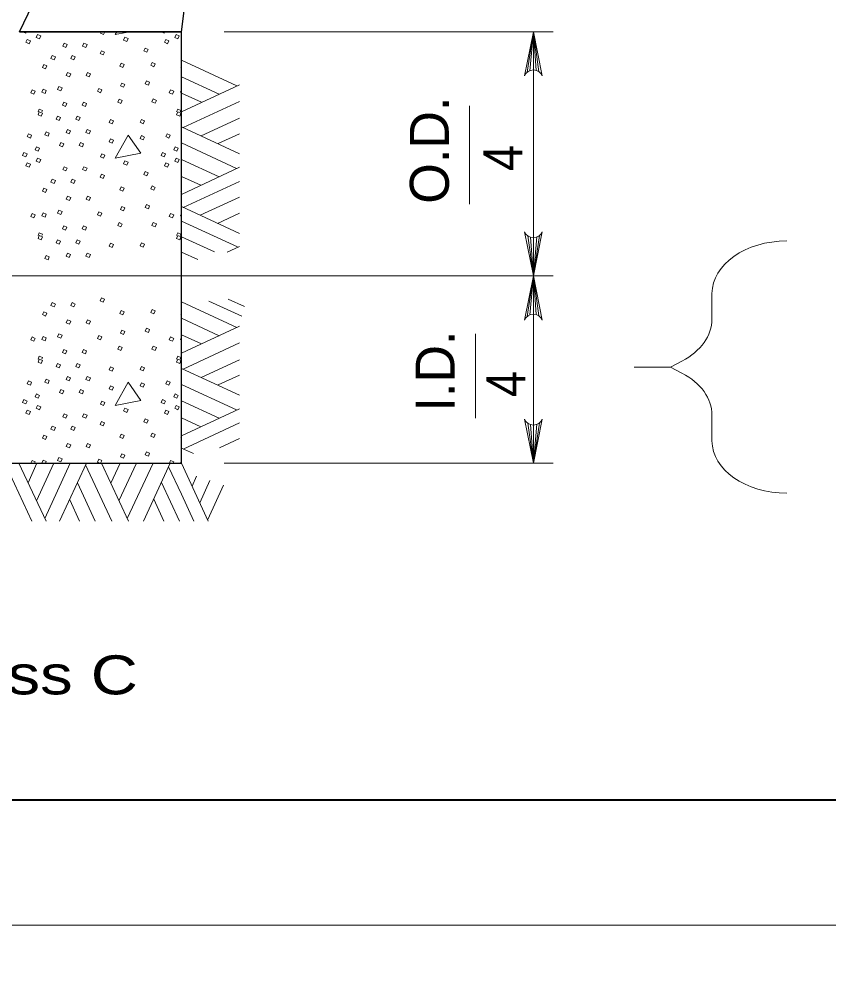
# Model space of a CAD drawing. Extents: x 1083.1 to 1117.1, y 697.4 to 741.4.
# Drawn here: x 1094.266 to 1097.505, y 719.104 to 722.978 of the extents above; entities that cross this region are included whole.
import ezdxf
from ezdxf.enums import TextEntityAlignment as Align

# ---------------------------------------------------------------- set-up
doc = ezdxf.new("R2010")
doc.units = 0
doc.header["$LTSCALE"] = 0.062
doc.linetypes.add('LONG_DASHED', pattern=[7.5, 6, -1.5])
doc.layers.add('1', color=7, linetype='Continuous', lineweight=13)

msp = doc.modelspace()

# ---------------------------------------------------------------- linework, layer by layer
at = {"layer": '1', "lineweight": 25}
for p, q in [((1094.915, 722.92817), (1095.17642, 725.01283)), ((1094.26642, 722.92817), (1094.915, 722.92817)), ((1094.26642, 722.92817), (1094.915, 722.92817))]:
    msp.add_line(p, q, dxfattribs=at)
at = {"layer": '1'}
for p, q in [((1094.915, 722.92817), (1094.26642, 722.92817)), ((1095.08633, 722.92817), (1096.40183, 722.92817)), ((1096.29833, 722.76608), (1096.32317, 722.92817)), ((1096.30875, 722.77217), (1096.32317, 722.92817)), ((1096.32317, 722.775), (1096.32317, 722.92817)), ((1096.3345, 722.77333), (1096.32317, 722.92817)), ((1096.34558, 722.76792), (1096.32317, 722.92817)), ((1094.915, 722.81433), (1095.13617, 722.71133)), ((1094.915, 722.74808), (1095.06567, 722.67817)), ((1094.915, 722.60825), (1095.14708, 722.71633)), ((1094.915, 722.68242), (1094.995, 722.64575)), ((1094.9215, 722.54483), (1095.14708, 722.64933)), ((1094.34125, 722.60725), (1094.34625, 722.61867)), ((1094.89558, 722.60725), (1094.90058, 722.61867)), ((1096.06708, 722.63183), (1096.06708, 722.23783)), ((1094.99358, 722.51175), (1095.14708, 722.58225)), ((1094.915, 722.54775), (1095.14708, 722.44033)), ((1095.06133, 722.48142), (1095.14708, 722.52033)), ((1094.915, 722.48358), (1095.1355, 722.38133)), ((1094.915, 722.41725), (1095.06567, 722.34817)), ((1094.915, 722.2775), (1095.14708, 722.38633)), ((1094.915, 722.3495), (1094.99283, 722.31425)), ((1094.92217, 722.22492), (1095.14708, 722.32942)), ((1094.98925, 722.19392), (1095.14708, 722.26667)), ((1094.915, 722.2285), (1095.14783, 722.12117)), ((1095.05917, 722.1615), (1095.14708, 722.20183)), ((1094.915, 722.17083), (1095.13983, 722.06708)), ((1094.34125, 722.11283), (1094.34625, 722.12425)), ((1094.89558, 722.11283), (1094.90058, 722.12425)), ((1094.915, 722.1075), (1095.04683, 722.04733)), ((1096.30075, 722.1115), (1096.32317, 721.95125)), ((1096.34792, 722.11342), (1096.32317, 721.95125)), ((1096.33758, 722.10725), (1096.32317, 721.95125)), ((1095.0985, 722.04683), (1095.14708, 722.06925)), ((1096.31183, 722.10608), (1096.32317, 721.95125)), ((1096.32317, 722.10442), (1096.32317, 721.95125)), ((1094.915, 722.04617), (1094.98, 722.0165)), ((1093.40175, 721.95125), (1096.40183, 721.95125)), ((1096.29833, 721.78908), (1096.32317, 721.95125)), ((1096.30875, 721.79525), (1096.32317, 721.95125)), ((1096.32317, 721.79808), (1096.32317, 721.95125)), ((1096.3345, 721.79642), (1096.32317, 721.95125)), ((1096.34558, 721.791), (1096.32317, 721.95125)), ((1097.03783, 721.88125), (1097.03783, 721.7785)), ((1094.915, 721.848), (1095.13617, 721.745)), ((1095.02442, 721.85092), (1095.15625, 721.79075)), ((1095.102, 721.85808), (1095.16692, 721.82833)), ((1094.915, 721.78175), (1095.06567, 721.71192)), ((1094.915, 721.64192), (1095.14708, 721.75008)), ((1096.09108, 721.71983), (1096.09108, 721.38208)), ((1094.915, 721.71617), (1094.995, 721.67942)), ((1094.9215, 721.57858), (1095.14708, 721.683)), ((1094.34125, 721.61833), (1094.34625, 721.62975)), ((1094.89558, 721.61833), (1094.90058, 721.62975)), ((1094.99358, 721.54542), (1095.14708, 721.61608)), ((1096.87208, 721.5865), (1096.91767, 721.6105)), ((1094.915, 721.5815), (1095.14708, 721.474)), ((1096.87208, 721.5865), (1096.7265, 721.5865)), ((1096.87208, 721.5865), (1096.91767, 721.5625)), ((1095.06133, 721.51508), (1095.14708, 721.55408)), ((1094.915, 721.51733), (1095.1355, 721.415)), ((1094.915, 721.45108), (1095.06567, 721.38175)), ((1094.915, 721.31125), (1095.14708, 721.42008)), ((1094.915, 721.38325), (1094.99283, 721.348)), ((1097.03783, 721.3945), (1097.03783, 721.29183)), ((1094.92217, 721.25867), (1095.14708, 721.36308)), ((1096.30075, 721.36192), (1096.32317, 721.20167)), ((1096.31183, 721.3565), (1096.32317, 721.20167)), ((1096.34792, 721.36383), (1096.32317, 721.20167)), ((1096.33758, 721.35767), (1096.32317, 721.20167)), ((1096.32317, 721.35483), (1096.32317, 721.20167)), ((1095.0675, 721.26375), (1095.14708, 721.30042)), ((1094.915, 721.26225), (1094.96267, 721.24025)), ((1094.21167, 721.1945), (1094.31617, 720.96958)), ((1094.26425, 721.20167), (1094.37308, 720.96958)), ((1094.33625, 721.20167), (1094.301, 721.12383)), ((1094.3125, 721.20167), (1094.31725, 721.2125)), ((1094.40408, 721.20167), (1094.33492, 721.05108)), ((1094.47033, 721.20167), (1094.36808, 720.98125)), ((1094.5345, 721.20167), (1094.42717, 720.96958)), ((1094.53158, 721.19517), (1094.63617, 720.96958)), ((1094.59508, 721.20167), (1094.70308, 720.96958)), ((1094.66925, 721.20167), (1094.63258, 721.12175)), ((1094.73492, 721.20167), (1094.66492, 721.05108)), ((1094.80117, 721.20167), (1094.69808, 720.9805)), ((1094.87033, 721.20167), (1094.763, 720.96958)), ((1094.86383, 721.18733), (1094.915, 721.07775)), ((1094.86683, 721.20167), (1094.87158, 721.2125)), ((1094.915, 721.20167), (1095.02233, 720.96958)), ((1095.08633, 721.20167), (1096.40183, 721.20167)), ((1094.97575, 721.15008), (1094.9575, 721.11017)), ((1094.4985, 721.12317), (1094.56908, 720.96958)), ((1094.83508, 721.12533), (1094.90783, 720.96958)), ((1095.02892, 721.1325), (1094.9885, 721.04392)), ((1095.08375, 721.11442), (1095.02025, 720.97683)), ((1094.915, 721.07775), (1094.96467, 720.96958)), ((1094.46825, 721.05533), (1094.50708, 720.96958)), ((1094.80408, 721.05825), (1094.84433, 720.96958))]:
    msp.add_line(p, q, dxfattribs=at)
at = {"layer": '1', "linetype": 'LONG_DASHED'}
for points in [[(1083.12642, 719.35408), (1117.12642, 719.35408), (1117.12642, 741.35408), (1083.12642, 741.35408)], [(1083.12642, 697.35408), (1117.12642, 697.35408), (1117.12642, 719.35408), (1083.12642, 719.35408)]]:
    msp.add_lwpolyline(points, close=True, dxfattribs=at)
at = {"layer": '1', "lineweight": 25}
for points in [[(1116.62642, 719.85408), (1085.12642, 719.85408), (1085.12642, 740.85408)], [(1091.06575, 722.92817), (1090.41717, 722.92817), (1090.41717, 721.20167), (1094.915, 721.20167), (1094.915, 722.92817)], [(1090.41717, 722.92817), (1090.41717, 721.20167), (1094.915, 721.20167), (1094.915, 722.92817), (1094.26642, 722.92817)]]:
    msp.add_lwpolyline(points, dxfattribs=at)
at = {"layer": '1', "lineweight": 40}
msp.add_lwpolyline([(1085.12642, 740.85408), (1116.62642, 740.85408), (1116.62642, 719.85408), (1085.12642, 719.85408)], close=True, dxfattribs=at)
msp.add_lwpolyline([(1085.12642, 740.85408), (1116.62642, 740.85408), (1116.62642, 719.85408), (1085.12642, 719.85408)], close=True, dxfattribs=at)
at = {"layer": '1'}
for points in [[(1094.29442, 722.92817), (1094.29192, 722.92242), (1094.27942, 722.92783), (1094.27958, 722.92817)], [(1094.60842, 722.92817), (1094.60342, 722.91675), (1094.59092, 722.92217), (1094.59358, 722.92817)], [(1094.65608, 722.92817), (1094.64958, 722.91667), (1094.70842, 722.92817)], [(1094.84875, 722.92817), (1094.84625, 722.92242), (1094.83375, 722.92783), (1094.83392, 722.92817)], [(1096.28775, 722.75117), (1096.32317, 722.92817), (1096.35858, 722.75117)], [(1096.32317, 722.92817), (1096.32317, 721.95125), (1096.32317, 721.20167)], [(1094.915, 722.78442), (1094.91317, 722.78525), (1094.915, 722.78958)], [(1094.915, 722.68442), (1094.911, 722.68617), (1094.915, 722.69542)], [(1094.34625, 722.61867), (1094.35875, 722.61325), (1094.35617, 722.60725)], [(1094.90058, 722.61867), (1094.913, 722.61325), (1094.9105, 722.60725)], [(1094.915, 722.29), (1094.91317, 722.29083), (1094.915, 722.29508)], [(1094.915, 722.18992), (1094.911, 722.19167), (1094.915, 722.201)], [(1094.34625, 722.12425), (1094.35875, 722.11883), (1094.35617, 722.11283)], [(1094.90058, 722.12425), (1094.913, 722.11883), (1094.9105, 722.11283)], [(1096.35858, 722.12825), (1096.32317, 721.95125), (1096.28775, 722.12825)], [(1096.28775, 721.77425), (1096.32317, 721.95125), (1096.35858, 721.77425)], [(1094.915, 721.7955), (1094.91317, 721.79633), (1094.915, 721.80067)], [(1094.915, 721.6955), (1094.911, 721.69725), (1094.915, 721.7065)], [(1094.34625, 721.62975), (1094.35875, 721.62433), (1094.35617, 721.61833)], [(1094.90058, 721.62975), (1094.913, 721.62433), (1094.9105, 721.61833)], [(1096.35858, 721.37867), (1096.32317, 721.20167), (1096.28775, 721.37867)], [(1094.915, 721.30108), (1094.91317, 721.30183), (1094.915, 721.30617)], [(1094.58958, 721.20167), (1094.57883, 721.20633), (1094.584, 721.21817)], [(1094.584, 721.21817), (1094.5965, 721.21275), (1094.59167, 721.20167)], [(1094.31725, 721.2125), (1094.32975, 721.20708), (1094.32733, 721.20167)], [(1094.35908, 721.20167), (1094.35667, 721.20275), (1094.36183, 721.21458)], [(1094.36183, 721.21458), (1094.37433, 721.20917), (1094.371, 721.20167)], [(1094.87158, 721.2125), (1094.88408, 721.20708), (1094.88167, 721.20167)], [(1094.91342, 721.20167), (1094.911, 721.20275), (1094.915, 721.212)]]:
    msp.add_lwpolyline(points, dxfattribs=at)
for points in [[(1094.29808, 722.89758), (1094.31058, 722.89217), (1094.30542, 722.88033), (1094.29292, 722.88575)], [(1094.33917, 722.91675), (1094.35167, 722.91133), (1094.3465, 722.8995), (1094.334, 722.90492)], [(1094.44533, 722.88275), (1094.45783, 722.87742), (1094.45267, 722.86558), (1094.44017, 722.871)], [(1094.52458, 722.88275), (1094.53708, 722.87742), (1094.53192, 722.86558), (1094.51942, 722.871)], [(1094.68883, 722.90608), (1094.70133, 722.90067), (1094.69617, 722.88883), (1094.68367, 722.89425)], [(1094.85242, 722.89758), (1094.86492, 722.89217), (1094.85975, 722.88033), (1094.84725, 722.88575)], [(1094.8935, 722.91675), (1094.906, 722.91133), (1094.90083, 722.8995), (1094.88833, 722.90492)], [(1094.59467, 722.85233), (1094.60717, 722.84692), (1094.602, 722.83508), (1094.5895, 722.8405)], [(1094.7695, 722.863), (1094.782, 722.85758), (1094.77683, 722.84575), (1094.76433, 722.85117)], [(1094.39792, 722.83325), (1094.41042, 722.82783), (1094.40525, 722.816), (1094.39275, 722.82142)], [(1094.47717, 722.83325), (1094.48967, 722.82783), (1094.4845, 722.816), (1094.472, 722.82142)], [(1094.79717, 722.80558), (1094.80967, 722.80017), (1094.8045, 722.78833), (1094.792, 722.79375)], [(1094.364, 722.79708), (1094.3765, 722.79167), (1094.37133, 722.77983), (1094.35883, 722.78525)], [(1094.67325, 722.80208), (1094.68575, 722.79667), (1094.68058, 722.78483), (1094.66808, 722.79025)], [(1094.4595, 722.7645), (1094.472, 722.75908), (1094.46683, 722.74725), (1094.45433, 722.75267)], [(1094.53875, 722.7645), (1094.55125, 722.75908), (1094.54608, 722.74725), (1094.53358, 722.75267)], [(1094.77517, 722.73125), (1094.78767, 722.72592), (1094.7825, 722.71408), (1094.77, 722.7195)], [(1094.31725, 722.69592), (1094.32975, 722.6905), (1094.32458, 722.67867), (1094.31208, 722.68408)], [(1094.36183, 722.698), (1094.37433, 722.69258), (1094.36917, 722.68075), (1094.35667, 722.68617)], [(1094.42483, 722.70867), (1094.43733, 722.70325), (1094.43217, 722.69142), (1094.41967, 722.69683)], [(1094.584, 722.70158), (1094.5965, 722.69617), (1094.59133, 722.68433), (1094.57883, 722.68975)], [(1094.67617, 722.723), (1094.68867, 722.71758), (1094.6835, 722.70575), (1094.671, 722.71117)], [(1094.87158, 722.69592), (1094.88408, 722.6905), (1094.87892, 722.67867), (1094.86642, 722.68408)], [(1094.66575, 722.65883), (1094.67825, 722.65342), (1094.67308, 722.64158), (1094.66058, 722.647)], [(1094.80208, 722.65908), (1094.81458, 722.65367), (1094.80942, 722.64183), (1094.79692, 722.64725)], [(1094.44392, 722.64633), (1094.45642, 722.64092), (1094.45125, 722.62908), (1094.43875, 722.6345)], [(1094.52317, 722.64633), (1094.53567, 722.64092), (1094.5305, 722.62908), (1094.518, 722.6345)], [(1094.34625, 722.60725), (1094.35875, 722.60183), (1094.35358, 722.59008), (1094.34108, 722.59542)], [(1094.41842, 722.59033), (1094.43092, 722.58492), (1094.42575, 722.57308), (1094.41325, 722.5785)], [(1094.49767, 722.59033), (1094.51017, 722.58492), (1094.505, 722.57308), (1094.4925, 722.5785)], [(1094.63075, 722.57692), (1094.64325, 722.5715), (1094.63808, 722.55967), (1094.62558, 722.56508)], [(1094.75467, 722.57758), (1094.76717, 722.57217), (1094.762, 722.56033), (1094.7495, 722.56575)], [(1094.90058, 722.60725), (1094.913, 722.60183), (1094.90792, 722.59008), (1094.89542, 722.59542)], [(1094.45883, 722.53725), (1094.47133, 722.53183), (1094.46617, 722.52), (1094.45367, 722.52542)], [(1094.53808, 722.53725), (1094.55058, 722.53183), (1094.54542, 722.52), (1094.53292, 722.52542)], [(1094.30308, 722.52025), (1094.31558, 722.51483), (1094.31042, 722.503), (1094.29792, 722.50842)], [(1094.37392, 722.52733), (1094.38633, 722.52192), (1094.38125, 722.51008), (1094.36875, 722.5155)], [(1094.6305, 722.50017), (1094.643, 722.49475), (1094.63783, 722.48292), (1094.62533, 722.48833)], [(1094.70183, 722.51483), (1094.64958, 722.42225), (1094.75183, 722.44225)], [(1094.75467, 722.51242), (1094.76717, 722.507), (1094.762, 722.49517), (1094.7495, 722.50058)], [(1094.85742, 722.52025), (1094.86992, 722.51483), (1094.86475, 722.503), (1094.85225, 722.50842)], [(1094.33492, 722.46783), (1094.34742, 722.46242), (1094.34225, 722.45058), (1094.32975, 722.456)], [(1094.43192, 722.4855), (1094.44442, 722.48008), (1094.43925, 722.46825), (1094.42675, 722.47367)], [(1094.51117, 722.4855), (1094.52367, 722.48008), (1094.5185, 722.46825), (1094.506, 722.47367)], [(1094.88925, 722.46783), (1094.90175, 722.46242), (1094.89658, 722.45058), (1094.88408, 722.456)], [(1094.28458, 722.44525), (1094.29708, 722.43983), (1094.29192, 722.428), (1094.27942, 722.43342)], [(1094.33917, 722.42233), (1094.35167, 722.41692), (1094.3465, 722.40508), (1094.334, 722.4105)], [(1094.59608, 722.43958), (1094.60858, 722.43417), (1094.60342, 722.42233), (1094.59092, 722.42775)], [(1094.83892, 722.44525), (1094.85142, 722.43983), (1094.84625, 722.428), (1094.83375, 722.43342)], [(1094.8935, 722.42233), (1094.906, 722.41692), (1094.90083, 722.40508), (1094.88833, 722.4105)], [(1094.29808, 722.40317), (1094.31058, 722.39775), (1094.30542, 722.38592), (1094.29292, 722.39133)], [(1094.44533, 722.38833), (1094.45783, 722.38292), (1094.45267, 722.37108), (1094.44017, 722.3765)], [(1094.52458, 722.38833), (1094.53708, 722.38292), (1094.53192, 722.37108), (1094.51942, 722.3765)], [(1094.68883, 722.41167), (1094.70133, 722.40625), (1094.69617, 722.39442), (1094.68367, 722.39983)], [(1094.85242, 722.40317), (1094.86492, 722.39775), (1094.85975, 722.38592), (1094.84725, 722.39133)], [(1094.39792, 722.33875), (1094.41042, 722.33333), (1094.40525, 722.3215), (1094.39275, 722.32692)], [(1094.47717, 722.33875), (1094.48967, 722.33333), (1094.4845, 722.3215), (1094.472, 722.32692)], [(1094.59467, 722.35783), (1094.60717, 722.35242), (1094.602, 722.34058), (1094.5895, 722.346)], [(1094.7695, 722.3685), (1094.782, 722.36308), (1094.77683, 722.35125), (1094.76433, 722.35667)], [(1094.364, 722.30267), (1094.3765, 722.29725), (1094.37133, 722.28542), (1094.35883, 722.29083)], [(1094.67325, 722.30758), (1094.68575, 722.30217), (1094.68058, 722.29042), (1094.66808, 722.29583)], [(1094.79717, 722.31108), (1094.80967, 722.30567), (1094.8045, 722.29392), (1094.792, 722.29933)], [(1094.4595, 722.27008), (1094.472, 722.26467), (1094.46683, 722.25283), (1094.45433, 722.25825)], [(1094.53875, 722.27008), (1094.55125, 722.26467), (1094.54608, 722.25283), (1094.53358, 722.25825)], [(1094.67617, 722.2285), (1094.68867, 722.22308), (1094.6835, 722.21125), (1094.671, 722.21667)], [(1094.77517, 722.23683), (1094.78767, 722.23142), (1094.7825, 722.21958), (1094.77, 722.225)], [(1094.31725, 722.20142), (1094.32975, 722.196), (1094.32458, 722.18417), (1094.31208, 722.18958)], [(1094.36183, 722.2035), (1094.37433, 722.19808), (1094.36917, 722.18625), (1094.35667, 722.19167)], [(1094.42483, 722.21417), (1094.43733, 722.20875), (1094.43217, 722.19692), (1094.41967, 722.20233)], [(1094.584, 722.20708), (1094.5965, 722.20167), (1094.59133, 722.18983), (1094.57883, 722.19525)], [(1094.87158, 722.20142), (1094.88408, 722.196), (1094.87892, 722.18417), (1094.86642, 722.18958)], [(1094.44392, 722.15192), (1094.45642, 722.1465), (1094.45125, 722.13467), (1094.43875, 722.14008)], [(1094.52317, 722.15192), (1094.53567, 722.1465), (1094.5305, 722.13467), (1094.518, 722.14008)], [(1094.66575, 722.16433), (1094.67825, 722.15892), (1094.67308, 722.14717), (1094.66058, 722.15258)], [(1094.80208, 722.16458), (1094.81458, 722.15917), (1094.80942, 722.14742), (1094.79692, 722.15283)], [(1094.34625, 722.11283), (1094.35875, 722.10742), (1094.35358, 722.09558), (1094.34108, 722.101)], [(1094.90058, 722.11283), (1094.913, 722.10742), (1094.90792, 722.09558), (1094.89542, 722.101)], [(1094.41842, 722.09583), (1094.43092, 722.09042), (1094.42575, 722.07858), (1094.41325, 722.084)], [(1094.49767, 722.09583), (1094.51017, 722.09042), (1094.505, 722.07858), (1094.4925, 722.084)], [(1094.63075, 722.08242), (1094.64325, 722.077), (1094.63808, 722.06517), (1094.62558, 722.07058)], [(1094.75467, 722.08308), (1094.76717, 722.07767), (1094.762, 722.06583), (1094.7495, 722.07125)], [(1094.37392, 722.03283), (1094.38633, 722.02742), (1094.38125, 722.01567), (1094.36875, 722.021)], [(1094.45883, 722.04275), (1094.47133, 722.03733), (1094.46617, 722.0255), (1094.45367, 722.03092)], [(1094.53808, 722.04275), (1094.55058, 722.03733), (1094.54542, 722.0255), (1094.53292, 722.03092)], [(1094.39792, 721.84433), (1094.41042, 721.83892), (1094.40525, 721.82708), (1094.39275, 721.8325)], [(1094.47717, 721.84433), (1094.48967, 721.83892), (1094.4845, 721.82708), (1094.472, 721.8325)], [(1094.59467, 721.86342), (1094.60717, 721.858), (1094.602, 721.84617), (1094.5895, 721.85158)], [(1094.364, 721.80817), (1094.3765, 721.80275), (1094.37133, 721.79092), (1094.35883, 721.79633)], [(1094.67325, 721.81317), (1094.68575, 721.80775), (1094.68058, 721.79592), (1094.66808, 721.80133)], [(1094.79717, 721.81667), (1094.80967, 721.81125), (1094.8045, 721.79942), (1094.792, 721.80483)], [(1094.4595, 721.77558), (1094.472, 721.77017), (1094.46683, 721.75833), (1094.45433, 721.76375)], [(1094.53875, 721.77558), (1094.55125, 721.77017), (1094.54608, 721.75833), (1094.53358, 721.76375)], [(1094.42483, 721.71975), (1094.43733, 721.71433), (1094.43217, 721.7025), (1094.41967, 721.70792)], [(1094.67617, 721.734), (1094.68867, 721.72858), (1094.6835, 721.71683), (1094.671, 721.72225)], [(1094.77517, 721.74233), (1094.78767, 721.73692), (1094.7825, 721.72517), (1094.77, 721.7305)], [(1094.31725, 721.707), (1094.32975, 721.70158), (1094.32458, 721.68975), (1094.31208, 721.69517)], [(1094.36183, 721.70908), (1094.37433, 721.70367), (1094.36917, 721.69183), (1094.35667, 721.69725)], [(1094.584, 721.71267), (1094.5965, 721.70725), (1094.59133, 721.69542), (1094.57883, 721.70083)], [(1094.87158, 721.707), (1094.88408, 721.70158), (1094.87892, 721.68975), (1094.86642, 721.69517)], [(1094.44392, 721.65742), (1094.45642, 721.652), (1094.45125, 721.64017), (1094.43875, 721.64558)], [(1094.52317, 721.65742), (1094.53567, 721.652), (1094.5305, 721.64017), (1094.518, 721.64558)], [(1094.66575, 721.66992), (1094.67825, 721.6645), (1094.67308, 721.65267), (1094.66058, 721.65808)], [(1094.80208, 721.67017), (1094.81458, 721.66475), (1094.80942, 721.65292), (1094.79692, 721.65833)], [(1094.34625, 721.61833), (1094.35875, 721.61292), (1094.35358, 721.60108), (1094.34108, 721.6065)], [(1094.90058, 721.61833), (1094.913, 721.61292), (1094.90792, 721.60108), (1094.89542, 721.6065)], [(1094.41842, 721.60133), (1094.43092, 721.59592), (1094.42575, 721.58417), (1094.41325, 721.5895)], [(1094.49767, 721.60133), (1094.51017, 721.59592), (1094.505, 721.58417), (1094.4925, 721.5895)], [(1094.63075, 721.58792), (1094.64325, 721.58258), (1094.63808, 721.57075), (1094.62558, 721.57617)], [(1094.75467, 721.58858), (1094.76717, 721.58325), (1094.762, 721.57142), (1094.7495, 721.57683)], [(1094.30308, 721.53133), (1094.31558, 721.52592), (1094.31042, 721.51408), (1094.29792, 721.5195)], [(1094.37392, 721.53842), (1094.38633, 721.533), (1094.38125, 721.52117), (1094.36875, 721.52658)], [(1094.45883, 721.54833), (1094.47133, 721.54292), (1094.46617, 721.53108), (1094.45367, 721.5365)], [(1094.53808, 721.54833), (1094.55058, 721.54292), (1094.54542, 721.53108), (1094.53292, 721.5365)], [(1094.70183, 721.52592), (1094.64958, 721.43333), (1094.75183, 721.45325)], [(1094.85742, 721.53133), (1094.86992, 721.52592), (1094.86475, 721.51408), (1094.85225, 721.5195)], [(1094.43192, 721.49658), (1094.44442, 721.49117), (1094.43925, 721.47933), (1094.42675, 721.48475)], [(1094.51117, 721.49658), (1094.52367, 721.49117), (1094.5185, 721.47933), (1094.506, 721.48475)], [(1094.6305, 721.51125), (1094.643, 721.50583), (1094.63783, 721.494), (1094.62533, 721.49942)], [(1094.75467, 721.5235), (1094.76717, 721.51808), (1094.762, 721.50625), (1094.7495, 721.51167)], [(1094.28458, 721.45625), (1094.29708, 721.45083), (1094.29192, 721.43908), (1094.27942, 721.44442)], [(1094.33492, 721.47892), (1094.34742, 721.4735), (1094.34225, 721.46167), (1094.32975, 721.46708)], [(1094.59608, 721.45058), (1094.60858, 721.44517), (1094.60342, 721.43342), (1094.59092, 721.43883)], [(1094.83892, 721.45625), (1094.85142, 721.45083), (1094.84625, 721.43908), (1094.83375, 721.44442)], [(1094.88925, 721.47892), (1094.90175, 721.4735), (1094.89658, 721.46167), (1094.88408, 721.46708)], [(1094.29808, 721.41425), (1094.31058, 721.40883), (1094.30542, 721.397), (1094.29292, 721.40242)], [(1094.33917, 721.43342), (1094.35167, 721.428), (1094.3465, 721.41617), (1094.334, 721.42158)], [(1094.68883, 721.42275), (1094.70133, 721.41733), (1094.69617, 721.4055), (1094.68367, 721.41092)], [(1094.85242, 721.41425), (1094.86492, 721.40883), (1094.85975, 721.397), (1094.84725, 721.40242)], [(1094.8935, 721.43342), (1094.906, 721.428), (1094.90083, 721.41617), (1094.88833, 721.42158)], [(1094.44533, 721.39942), (1094.45783, 721.394), (1094.45267, 721.38217), (1094.44017, 721.38758)], [(1094.52458, 721.39942), (1094.53708, 721.394), (1094.53192, 721.38217), (1094.51942, 721.38758)], [(1094.7695, 721.37958), (1094.782, 721.37417), (1094.77683, 721.36233), (1094.76433, 721.36775)], [(1094.39792, 721.34983), (1094.41042, 721.34442), (1094.40525, 721.33258), (1094.39275, 721.338)], [(1094.47717, 721.34983), (1094.48967, 721.34442), (1094.4845, 721.33258), (1094.472, 721.338)], [(1094.59467, 721.36892), (1094.60717, 721.3635), (1094.602, 721.35167), (1094.5895, 721.35708)], [(1094.364, 721.31367), (1094.3765, 721.30825), (1094.37133, 721.2965), (1094.35883, 721.30183)], [(1094.67325, 721.31867), (1094.68575, 721.31325), (1094.68058, 721.30142), (1094.66808, 721.30683)], [(1094.79717, 721.32217), (1094.80967, 721.31675), (1094.8045, 721.30492), (1094.792, 721.31033)], [(1094.4595, 721.28117), (1094.472, 721.27575), (1094.46683, 721.26392), (1094.45433, 721.26933)], [(1094.53875, 721.28117), (1094.55125, 721.27575), (1094.54608, 721.26392), (1094.53358, 721.26933)], [(1094.42483, 721.22525), (1094.43733, 721.21983), (1094.43217, 721.208), (1094.41967, 721.21342)], [(1094.67617, 721.23958), (1094.68867, 721.23417), (1094.6835, 721.22233), (1094.671, 721.22775)], [(1094.77517, 721.24792), (1094.78767, 721.2425), (1094.7825, 721.23067), (1094.77, 721.23608)]]:
    msp.add_lwpolyline(points, close=True, dxfattribs=at)
for centre, start, end in [((1096.32319, 722.7369), 22.08782, 157.91395), ((1096.32311, 722.14255), 202.08782, 337.91395), ((1096.32319, 721.75996), 22.08782, 157.91395), ((1096.32311, 721.39298), 202.08782, 337.91395)]:
    msp.add_arc(centre, 0.0382, start, end, dxfattribs=at)
at = {"layer": '1', "lineweight": 25}
msp.add_ellipse((1092.66607, 723.75022), major_axis=(1.79915, 0), ratio=0.999895, start_param=5.8086305, end_param=9.8993328, dxfattribs=at)
msp.add_ellipse((1092.66607, 723.75022), major_axis=(1.79915, 0), ratio=0.999895, start_param=5.8086305, end_param=9.8993328, dxfattribs=at)
at = {"layer": '1'}
for centre, major_axis, start_param, end_param in [((1097.33771, 721.88123), (-0.29986, 0), 4.712389, 6.2831853), ((1096.73799, 721.77852), (0.29986, 0), 5.3548956, 6.2831853), ((1096.73799, 721.3945), (0.29986, 0), 6.2831853, 7.2111816), ((1097.33771, 721.29182), (-0.29986, 0), 6.2831853, 7.8539816)]:
    msp.add_ellipse(centre, major_axis=major_axis, ratio=0.699926, start_param=start_param, end_param=end_param, dxfattribs=at)

# ---------------------------------------------------------------- texts
for s, p in [('O.D.', (1095.98492, 722.45438)), ('I.D.', (1096.00792, 721.57071))]:
    msp.add_text(s, height=0.156, rotation=90, dxfattribs=at).set_placement(p, align=Align.CENTER)
at = {"layer": '1', "width": 0.9}
for p in [(1096.27883, 722.42346), (1096.29083, 721.51896)]:
    msp.add_text('4', height=0.156, rotation=90, dxfattribs=at).set_placement(p, align=Align.CENTER)
at = {"layer": '1', "width": 1.25}
msp.add_text('concrete cradle, Class C', height=0.156, dxfattribs=at).set_placement((1091.9, 720.27725))

doc.saveas('drawing.dxf')
